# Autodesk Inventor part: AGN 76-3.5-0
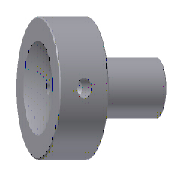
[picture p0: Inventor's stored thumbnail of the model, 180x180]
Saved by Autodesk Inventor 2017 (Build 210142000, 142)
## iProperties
IsCustomPart: 1
Created: 2016-02
Part Number: AGN 76-3.5-0
Material: DIN 1.2312
Description: Sprue Bushing
Document SubType Name: Modeling
Designer: Sandeep
Standard Revision: 1
Manufacturer: DME
Language: en-US
Size Designation: 76-3.5-0
Categories: <MemberInstance><Categories><Category DisplayName="Mold" InternalName="349578f2-f4d4-4954-8c09-8e99297a61c0" Mnemonic="MOLD"><Category DisplayName="Runners" Int
Density: 7.85 g/cm^3
Appearance: Default
Author: Sandeep
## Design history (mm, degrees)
sketch "Sketch1"
  geometry: L1 (0, -27.2)-(0, 23.2) reference; L2 (1.75, 20)-(19, 20); L3 (19, 20)-(19, 0); L4 (19, 0)-(12, 0); L5 (9, -3)-(9, -76); L6 (9, -76)-(4.264, -76); L7 (4.264, -76)-(1.75, 20); A1 r 3 centre (12, -3) between (12, 0) and (9, -3); 2 further points
  constraints: 12 end point, 3 parallel, 2 perpendicular, 2 point on circle, 2 point on line, 2 tangent, 1 centre point
  dimensions: "d0" = 18 diameter of L5 L1 (= D); "d3" = 38 diameter of L3 L1 (= d1); "d6" = 1.5 deg angle of L7 L1 (= 0.5 x Taper); "d7" = 20 distance between parallel lines of L4 L2 (= K_); "d8" = 76 distance between parallel lines of L4 L6 (= L); "d9" = 3 radius of A1 (= R3); "d62" = 3.5 diameter of point (1.75, 20) L1 (= d_); "d63" = 0 distance from line of point (1.75, 20) L2 (computed from Rd)
revolve "Revolution1" sketch "Sketch1" stored, may be unused: angle "d10" = 90 deg
sketch "Sketch2"
  geometry: L1 (0, -32.79)-(0, 56.739) reference; L2 (4.264, -76)-(1.75, 20) reference; L3 (-19, 20)-(19, 20) reference; L4 (0, 50.901)-(0, 19.901); A1 r 15.5 centre (0, 35.401) between (0, 19.901) and (0, 50.901); 2 further points
  constraints: 3 point on circle, 3 point on line, 2 end point, 1 centre point, 1 midpoint
  dimensions: "d64" = 0 distance from line of point (1.75, 20) L3 (computed from Rd); "d67" = 15.5 radius of A1 (= Rk)
revolve "Revolution2" sketch "Sketch2" stored, may be unused: angle "d13" = 90 deg
workplane "Work Plane1"
sketch "Sketch3"
  geometry: 2 further points
  constraints: 1 vertical alignment
  dimensions: "d43" = 10 distance of point (0, -10) point (0, 0) (= 0.5 x K_)
hole "Hole1" sketch "Sketch3" at (0, 0) diameter "d15" = 4 (= pd1); stored, may be unused: countersink angle "d19" = 90 deg, drill point angle "d21" = 118 deg; dims "d16" = 6, "d17" = 4, "d18" = 2, "d20" = 6 (= pl1)
chamfer "Chamfer1" distance "d22" = 0.3; stored, may be unused: second distance "d23" = 2, angle "d24" = 45 deg
sketch "Sketch4"
  geometry: L1 (0, -30.4)-(0, 42.4) reference; L2 (0, 40)-(19.5, 40); L3 (19.5, 40)-(19.5, 0); L4 (9, -76)-(0, -76); L5 (0, -76)-(0, 40); L6 (9, -3)-(9, -76); L7 (12, 0)-(19.5, 0); L8 (12, 0)-(9, -3); 2 further points
  constraints: 14 end point, 4 point on line, 2 horizontal, 2 parallel, 1 perpendicular, 1 vertical
  dimensions: "d56" = 3 distance of L7.start point (9, 0) (= R3_CS); "d57" = 3 distance of L6.start point (9, 0) (= d56); "d58" = 39 diameter of L3 L1 (= d1_CS); "d59" = 40 distance between parallel lines of L7 L2 (= K_CS); "d60" = 18 diameter of L6 L1 (= D_CS); "d61" = 76 distance between parallel lines of L7 L4 (= L_CS)
feature "RevolutionSrf1" sketch "Sketch4" dims angle "d33" = 90 deg
feature "Sculpt7"
split "Split7"
body "Solid1"
body "Srf1"
feature "Surface4"
body "Srf5"
other parameters: "L" = 76 [user parameter; used in 1 equation term], "d1" = 38 [user parameter; used in 1 equation term], "d_" = 3.5 [user parameter; used in 1 equation term], "D" = 18 [user parameter; used in 1 equation term], "K_" = 20 [user parameter; used in 2 equation terms], "R" = 0 [user parameter], "Taper" = 3 deg [user parameter; used in 1 equation term], "Rd" = 0 [user parameter; used in 2 equation terms], "R3" = 3 [user parameter; used in 1 equation term], "pd1" = 4 [user parameter; used in 1 equation term], "d1_CS" = 39 [user parameter; used in 1 equation term], "K_CS" = 40 [user parameter; used in 1 equation term], "d44" = 0, "d45" = 0, "d46" = 0, "L_CS" = 76 [user parameter; used in 1 equation term], "D_CS" = 18 [user parameter; used in 1 equation term], "pl1" = 6 [user parameter; used in 1 equation term], "R3_CS" = 3 [user parameter; used in 1 equation term], "Rk" = 15.5 [user parameter; used in 1 equation term]
